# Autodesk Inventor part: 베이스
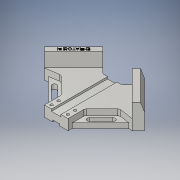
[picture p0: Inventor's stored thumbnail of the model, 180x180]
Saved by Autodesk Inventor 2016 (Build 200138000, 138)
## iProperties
Created: 2020-05
Part Number: 베이스
Material: 알루미늄 6061
Document SubType Name: Modeling
Designer: MIRAE
Density: 2.7 g/cm^3
Appearance: 알루미늄 - 평지
Mass: 571.622 g
Surface Area: 407.173 cm^2
Volume: 211.712 cm^3
Author: MIRAE
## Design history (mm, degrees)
sketch "스케치1"
  geometry: L1 (0, 0)-(84.853, 84.853); L2 (0, 0)-(120, 0); L3 (84.853, 84.853)-(0, 169.706); L4 (0, -33.941)-(0, 203.647) reference; L5 (-84.853, 84.853)-(0, 169.706); L6 (0, 0)-(-84.853, 84.853); L7 (-20, 20)-(20, 20); L8 (-35.355, 134.35)-(-16.005, 115); L9 (-16.005, 115)-(0, 115); L10 (16.005, 115)-(0, 115); L11 (16.005, 115)-(35.355, 134.35); L12 (-24.749, 123.744)-(-74.246, 74.246); L13 (24.749, 123.744)-(74.246, 74.246)
  constraints: 24 end point, 9 point on line, 4 perpendicular, 3 horizontal, 2 symmetric about line, 1 equal length
  dimensions: "d0" = 120 distance of L1.start L1.end; "d1" = 45 deg angle of L2 L1; "d2" = 120 distance of L1.end L3.end; "d3" = 20 distance from line of L1.start L7; "d4" = 90 deg angle of L8 L5; "d5" = 50 distance of L3.end L8.start; "d6" = 95 distance between parallel lines of L7 L9; "d7" = 15 distance of L5.start L12.end; "d8" = 15 distance of L13.end L1.end
extrude "돌출1" new body sketch "스케치1" distance "d9" = 18; taper "d10" = 0 deg
extrude "돌출2" join sketch "스케치1" distance "d11" = 42; taper "d12" = 0 deg
chamfer "모따기1" distance "d13" = 5; stored, may be unused: second distance "d14" = 15, angle "d15" = 45 deg
chamfer "모따기2" distance "d16" = 5; stored, may be unused: second distance "d17" = 15, angle "d18" = 45 deg
sketch "스케치2"
  geometry: L1 (-74.246, 74.246)-(-49.497, 77.782); L2 (-49.497, 77.782)-(-20, 48.284); L3 (-74.246, 74.246)-(-20, 20) reference; L4 (-20, 48.284)-(-20, 20); L5 (-20, 20)-(20, 20) reference; L6 (-35.355, 134.35)-(-84.853, 84.853) reference; L7 (-68.059, 75.13)-(-20, 27.071); L8 (-49.497, 66.468)-(-29.698, 46.669); L9 (-52.326, 63.64)-(-32.527, 43.841); L10 (-26.87, 49.497)-(-46.669, 69.296); L11 (-84.853, 84.853)-(-81.317, 81.317) reference; A1 r 4 centre (-49.497, 66.468) between (-46.669, 69.296) and (-52.326, 63.64); A2 r 4 centre (-29.698, 46.669) between (-32.527, 43.841) and (-26.87, 49.497); 2 further points
  constraints: 16 end point, 4 parallel, 4 point on circle, 4 tangent, 2 centre point, 2 point on line, 1 midpoint
  dimensions: "d19" = 90 deg angle of L5 L4; "d20" = 20 distance between parallel lines of L3 L2; "d21" = 30 distance from line of L6 L1.end; "d22" = 5 distance from line of L3 L7.start; "d23" = 28 distance of L8.start L8.end; "d24" = 8 diameter of A2; "d25" = 38 distance from line of L6 L8.start; "d26" = 12 distance between parallel lines of L11 L8
extrude "돌출3" cut sketch "스케치2" stored distance "d27" = 42; taper "d28" = 0 deg
extrude "돌출4" cut sketch "스케치2" stored distance "d29" = 42; taper "d30" = 0 deg
extrude "돌출5" cut sketch "스케치2" distance "d31" = 10; taper "d32" = 0 deg
fillet "모깎기1" dims "d33" = 5
fillet "모깎기2" dims "d34" = 5
sketch "스케치3"
  geometry: L1 (14, 3)-(26, 3); L2 (26, 3)-(26, -3); L3 (26, -3)-(14, -3); L4 (14, -3)-(14, 3); L5 (14, 3)-(26, -3); L6 (26, 3)-(14, -3); L7 (12, 21.5)-(28, 21.5); L8 (28, 21.5)-(28, 14.5); L9 (28, 14.5)-(12, 14.5); L10 (12, 14.5)-(12, 21.5); L11 (0, 18)-(40, 18) reference; L12 (12, 21.5)-(28, 14.5); L13 (28, 21.5)-(12, 14.5); 2 further points
  constraints: 24 end point, 5 midpoint, 4 parallel, 2 horizontal, 2 perpendicular
  dimensions: "d35" = 12 distance of L2.end L3.end; "d36" = 6 distance of L1.end L2.end; "d37" = 16 distance of L8.end L9.end; "d38" = 7 distance of L7.end L8.end
extrude "돌출6" cut sketch "스케치3" stored distance "d39" = 10; taper "d40" = 0 deg
sketch "스케치4"
  geometry: L1 (-6, 20)-(-20, 20) reference; L2 (-14, 20)-(-14, 26); L3 (-20, 27.071)-(-20, 20) reference; 1 further point
  constraints: 2 end point, 1 parallel, 1 point on line
  dimensions: "d42" = 6 distance of L2.start L2.end; "d43" = 14 horizontal distance of L2.start point (0, 0)
hole "구멍1" sketch "스케치4" at (-14, 26) diameter "d44" = 4.5; stored, may be unused: countersink angle "d48" = 90 deg, drill point angle "d50" = 118 deg; dims "d45" = 6, "d46" = 8, "d47" = 10, "d49" = 8
sketch "스케치5"
  geometry: L1 (-28.28, 127.283)-(-53.029, 102.534); L2 (-74.246, 74.246)-(-24.749, 123.744) reference; 2 further points
  constraints: 2 end point, 1 coincident, 1 parallel, 1 other
  dimensions: "d57" = 35 distance of L1.start L1.end; "d58" = 5 distance between parallel lines of L1 L2
feature "엠보싱1" sketch "스케치5" dims "d59" = 0.5, "d60" = 0
node "솔리드1"
mirror "대칭1"
pattern_linear "직사각형 패턴1" dims "d53" = 12, "d56" = 28
